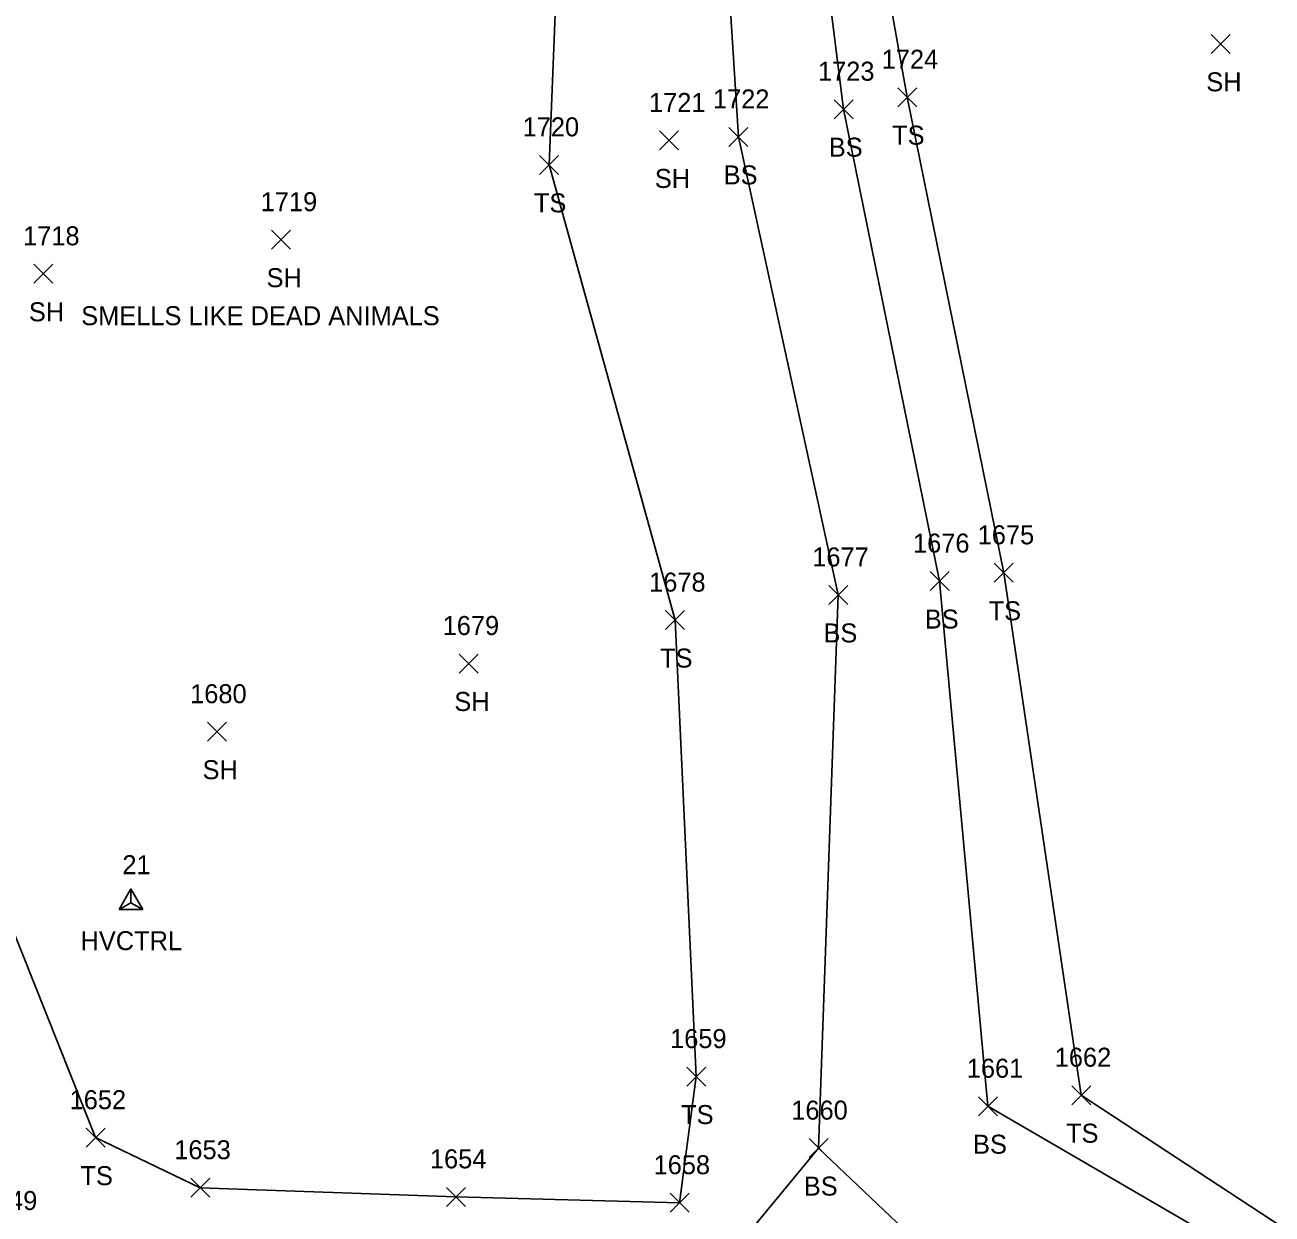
# Model space of a CAD drawing. Extents: x 1472233 to 1475777, y 540726 to 543442.
# Drawn here: x 1475192.5 to 1475323.8, y 543037.4 to 543162.6 of the extents above; entities that cross this region are included whole.
import ezdxf

# ---------------------------------------------------------------- set-up
doc = ezdxf.new("R2010")
doc.units = 0
for name, color, linetype in [('C_A', 7, 'Continuous'), ('C_I', 7, 'Continuous'), ('CPSM', 7, 'Continuous'), ('L_A', 7, 'Continuous'), ('L_C', 7, 'Continuous'), ('L_I', 7, 'Continuous'), ('L_TIC', 7, 'Continuous'), ('LELB', 7, 'Continuous')]:
    doc.layers.add(name, color=color, linetype=linetype)

msp = doc.modelspace()

# ---------------------------------------------------------------- linework, layer by layer
at = {"layer": 'CPSM'}
for p, q in [((1475202.4, 543069.5), (1475203.65, 543071.67)), ((1475204.9, 543069.5), (1475203.65, 543071.67)), ((1475203.65, 543070.22), (1475203.65, 543071.67)), ((1475202.4, 543069.5), (1475203.65, 543070.22)), ((1475202.4, 543069.5), (1475204.9, 543069.5)), ((1475203.65, 543070.22), (1475203.65, 543070.22)), ((1475203.65, 543070.22), (1475204.9, 543069.5))]:
    msp.add_line(p, q, dxfattribs=at)
at = {"layer": 'L_TIC'}
for points in [[(1475317.39, 543159.64), (1475319.39, 543161.64)], [(1475319.39, 543159.64), (1475317.39, 543161.64)], [(1475284.39, 543154.02), (1475286.39, 543156.02)], [(1475286.39, 543154.02), (1475284.39, 543156.02)], [(1475277.69, 543152.76), (1475279.69, 543154.76)], [(1475279.69, 543152.76), (1475277.69, 543154.76)], [(1475266.62, 543149.84), (1475268.62, 543151.84)], [(1475268.62, 543149.84), (1475266.62, 543151.84)], [(1475259.32, 543149.47), (1475261.32, 543151.47)], [(1475261.32, 543149.47), (1475259.32, 543151.47)], [(1475246.67, 543146.9), (1475248.67, 543148.9)], [(1475248.67, 543146.9), (1475246.67, 543148.9)], [(1475218.44, 543139.02), (1475220.44, 543141.02)], [(1475220.44, 543139.02), (1475218.44, 543141.02)], [(1475193.41, 543135.43), (1475195.41, 543137.43)], [(1475195.41, 543135.43), (1475193.41, 543137.43)], [(1475294.55, 543103.95), (1475296.55, 543105.95)], [(1475296.55, 543103.95), (1475294.55, 543105.95)], [(1475287.8, 543103.08), (1475289.8, 543105.08)], [(1475289.8, 543103.08), (1475287.8, 543105.08)], [(1475277.13, 543101.62), (1475279.13, 543103.62)], [(1475279.13, 543101.62), (1475277.13, 543103.62)], [(1475259.95, 543098.97), (1475261.95, 543100.97)], [(1475261.95, 543098.97), (1475259.95, 543100.97)], [(1475259.95, 543098.97), (1475261.95, 543100.97)], [(1475261.95, 543098.97), (1475259.95, 543100.97)], [(1475238.22, 543094.4), (1475240.22, 543096.4)], [(1475240.22, 543094.4), (1475238.22, 543096.4)], [(1475211.71, 543087.22), (1475213.71, 543089.22)], [(1475213.71, 543087.22), (1475211.71, 543089.22)], [(1475262.17, 543050.91), (1475264.17, 543052.91)], [(1475264.17, 543050.91), (1475262.17, 543052.91)], [(1475302.71, 543048.95), (1475304.71, 543050.95)], [(1475304.71, 543048.95), (1475302.71, 543050.95)], [(1475292.88, 543047.79), (1475294.88, 543049.79)], [(1475294.88, 543047.79), (1475292.88, 543049.79)], [(1475198.93, 543044.48), (1475200.93, 543046.48)], [(1475200.93, 543044.48), (1475198.93, 543046.48)], [(1475198.93, 543044.48), (1475200.93, 543046.48)], [(1475200.93, 543044.48), (1475198.93, 543046.48)], [(1475275.06, 543043.38), (1475277.06, 543045.38)], [(1475277.06, 543043.38), (1475275.06, 543045.38)], [(1475275.06, 543043.38), (1475277.06, 543045.38)], [(1475277.06, 543043.38), (1475275.06, 543045.38)], [(1475209.95, 543039.21), (1475211.95, 543041.21)], [(1475211.95, 543039.21), (1475209.95, 543041.21)], [(1475236.87, 543038.25), (1475238.87, 543040.25)], [(1475238.87, 543038.25), (1475236.87, 543040.25)], [(1475260.42, 543037.63), (1475262.42, 543039.63)], [(1475262.42, 543037.63), (1475260.42, 543039.63)]]:
    msp.add_lwpolyline(points, dxfattribs=at)
at = {"layer": 'LELB'}
for points in [[(1475637.4, 542862.19), (1475558.97, 542854.37), (1475522.58, 542847.01), (1475462.12, 542840.67), (1475427.68, 542835.08), (1475387.91, 542828.86), (1475376.04, 542829.87), (1475372.73, 542845.33), (1475367.24, 542869.75), (1475360.58, 542900.86), (1475350.02, 542943.33), (1475343.16, 542983.21), (1475336.52, 543023.98), (1475293.88, 543048.79), (1475288.8, 543104.08), (1475278.69, 543153.76), (1475270.93, 543215.65), (1475262.61, 543250.76), (1475255.19, 543261.13), (1475252.93, 543261.2), (1475255.17, 543243.69), (1475255.37, 543228.09)], [(1475351.79, 542648.85), (1475354.21, 542700.68), (1475359.1, 542754.23), (1475365.39, 542809), (1475353.96, 542862.01), (1475341.44, 542908.94), (1475326.71, 542945.92), (1475320.21, 542980.33), (1475313.2, 543006.73), (1475301.5, 543020.23), (1475276.06, 543044.38), (1475278.13, 543102.62), (1475267.62, 543150.84), (1475263.86, 543210.05), (1475244.31, 543220.04), (1475212.37, 543223.3), (1475177.58, 543227.73), (1475145.13, 543221.3), (1475130.45, 543212.37)], [(1475634.87, 542874.57), (1475554.98, 542871.91), (1475517.29, 542864.4), (1475459.45, 542859.45), (1475423.85, 542850.23), (1475393.53, 542836.58), (1475384.73, 542853.99), (1475376.54, 542871.34), (1475366.7, 542903.6), (1475357.98, 542945.38), (1475351.35, 542984.74), (1475343.94, 543023.57), (1475303.71, 543049.95), (1475295.55, 543104.95), (1475285.39, 543155.02), (1475274.49, 543216.06)], [(1475260.95, 543099.97), (1475247.67, 543147.9), (1475249.95, 543204.31), (1475207.64, 543205.47), (1475145.47, 543210.28), (1475133.24, 543194.28), (1475145.38, 543174.94)], [(1475199.93, 543045.48), (1475188.19, 543074.86), (1475167.63, 543130.05), (1475145.38, 543174.94)], [(1475199.93, 543045.48), (1475210.95, 543040.21), (1475237.87, 543039.25), (1475261.42, 543038.63), (1475263.17, 543051.91), (1475260.95, 543099.97)], [(1475190.59, 543034.86), (1475199, 543026.22), (1475214.28, 543024.29), (1475246.33, 543030.69), (1475265.09, 543031.12), (1475276.06, 543044.38)]]:
    msp.add_lwpolyline(points, dxfattribs=at)

# ---------------------------------------------------------------- texts
at = {"layer": 'C_A'}
msp.add_text('HVCTRL', height=2, dxfattribs=at).set_placement((1475198.34, 543065.22))
at = {"layer": 'C_I'}
msp.add_text('21', height=2, dxfattribs=at).set_placement((1475202.75, 543073.22))
at = {"layer": 'L_A'}
for s, p in [('SH', (1475316.88, 543155.64)), ('TS', (1475283.8, 543150.02)), ('BS', (1475277.13, 543148.76)), ('BS', (1475266.06, 543145.84)), ('SH', (1475258.81, 543145.47)), ('TS', (1475246.08, 543142.9)), ('SH', (1475217.93, 543135.02)), ('SH', (1475192.9, 543131.43)), ('TS', (1475293.96, 543099.95)), ('BS', (1475287.24, 543099.08)), ('BS', (1475276.57, 543097.62)), ('TS', (1475259.36, 543094.97)), ('TS', (1475259.36, 543094.97)), ('SH', (1475237.7, 543090.4)), ('SH', (1475211.19, 543083.22)), ('TS', (1475261.58, 543046.91)), ('TS', (1475302.11, 543044.95)), ('BS', (1475292.32, 543043.79)), ('TS', (1475198.33, 543040.48)), ('TS', (1475198.33, 543040.48)), ('BS', (1475274.5, 543039.38)), ('BS', (1475274.5, 543039.38))]:
    msp.add_text(s, height=2, dxfattribs=at).set_placement(p)
at = {"layer": 'L_C'}
msp.add_text('SMELLS LIKE DEAD ANIMALS', height=2, dxfattribs=at).set_placement((1475198.41, 543131.02))
at = {"layer": 'L_I'}
for s, p in [('1724', (1475282.7, 543158.02)), ('1723', (1475275.99, 543156.76)), ('1722', (1475264.93, 543153.84)), ('1721', (1475258.2, 543153.47)), ('1720', (1475244.89, 543150.9)), ('1719', (1475217.31, 543143.02)), ('1718', (1475192.29, 543139.43)), ('1675', (1475292.81, 543107.95)), ('1676', (1475286, 543107.08)), ('1677', (1475275.39, 543105.62)), ('1678', (1475258.21, 543102.97)), ('1678', (1475258.21, 543102.97)), ('1679', (1475236.47, 543098.4)), ('1680', (1475209.88, 543091.22)), ('1659', (1475260.42, 543054.91)), ('1662', (1475300.92, 543052.95)), ('1661', (1475291.66, 543051.79)), ('1652', (1475197.19, 543048.48)), ('1652', (1475197.19, 543048.48)), ('1660', (1475273.18, 543047.38)), ('1660', (1475273.18, 543047.38)), ('1653', (1475208.21, 543043.21)), ('1654', (1475235.13, 543042.25)), ('1658', (1475258.68, 543041.63)), ('1649', (1475187.84, 543037.86)), ('1649', (1475187.84, 543037.86))]:
    msp.add_text(s, height=2, dxfattribs=at).set_placement(p)

doc.saveas('drawing.dxf')
